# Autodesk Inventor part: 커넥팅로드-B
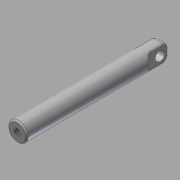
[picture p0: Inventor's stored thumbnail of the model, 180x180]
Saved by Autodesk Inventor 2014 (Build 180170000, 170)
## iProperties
Created: 2018-01
Part Number: 커넥팅로드-B
Material: 강철, 연강
Document SubType Name: Modeling
Designer: mduedu
Density: 7.86 g/cm^3
Appearance: 강철
Mass: 14.5817 g
Surface Area: 12.9188 cm^2
Volume: 1.85518 cm^3
Author: mduedu
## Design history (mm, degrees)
sketch "스케치1"
  geometry: C1 r 3.5 at (0, 0); 1 further point
  constraints: 1 centre point, 1 coincident
  dimensions: "d0" = 7 diameter of C1
extrude "돌출1" new body sketch "스케치1" distance "d1" = 53; taper "d2" = 0 deg
node "작업 평면1"
sketch "스케치2"
  geometry: L1 (-3.5, 0)-(3.5, 0) reference; L2 (4, 4)-(4, 0); L3 (4, 0)-(-4, 0); L4 (-4, 0)-(-4, 4); A1 r 4 centre (0, 4) between (4, 4) and (-4, 4); 2 further points
  constraints: 6 end point, 2 perpendicular, 2 point on circle, 2 tangent, 1 centre point, 1 collinear, 1 midpoint, 1 vertical, 1 vertical alignment
  dimensions: "d4" = 8 diameter of A1; "d5" = 4 distance from line of A1.centre L1
extrude "돌출2" cut sketch "스케치2" stored distance "d6" = 53; taper "d7" = 0 deg
fillet "모깎기1" dims "d8" = 2
fillet "모깎기2" dims "d9" = 0.5
fillet "모깎기3" dims "d10" = 0.5
sketch "스케치3"
  geometry: C1 r 1.75 at (0, 3); 1 further point
  constraints: 1 centre point, 1 vertical alignment
  dimensions: "d11" = 3.5 diameter of C1; "d12" = 3 distance of point (0, 0) C1.centre
extrude "돌출3" cut sketch "스케치3" stored distance "d13" = 53; taper "d14" = 0 deg
chamfer "모따기1" distance "d15" = 0.5; stored, may be unused: second distance "d16" = 2, angle "d17" = 45 deg
sketch "스케치4"
  geometry: 1 further point
hole "구멍1" sketch "스케치4" at (0, 0) diameter "d18" = 2.459; stored, may be unused: countersink angle "d22" = 90 deg, drill point angle "d24" = 120 deg; dims "d19" = 6.9, "d20" = 4, "d21" = 2, "d23" = 8.4
node "솔리드1"
mirror "대칭1"
other parameters: "d3" = 2
